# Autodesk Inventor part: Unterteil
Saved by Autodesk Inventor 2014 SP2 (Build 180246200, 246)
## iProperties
Created: 2015-06
Part Number: Unterteil
Material: Generisch
Document SubType Name: Modeling
Designer: e_krauts
Density: 1 g/cm^3
Appearance: Vorgabe
Sending System: SolidWorks 2011
Last Author: e_boekem
Author: e_krauts
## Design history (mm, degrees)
node "Unterteil.ipt1"
node "Aufsatz-Linear austragen3"
node "Basis1"
